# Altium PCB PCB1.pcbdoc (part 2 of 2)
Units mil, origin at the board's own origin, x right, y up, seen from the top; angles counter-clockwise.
Board outline 5175 x 2060 mil, 4 copper layers (Top Layer, Inner1, Inner2, Bottom Layer), stack 62.447 mil thick; 105 components, 59 nets, 317 pads, 174 vias.
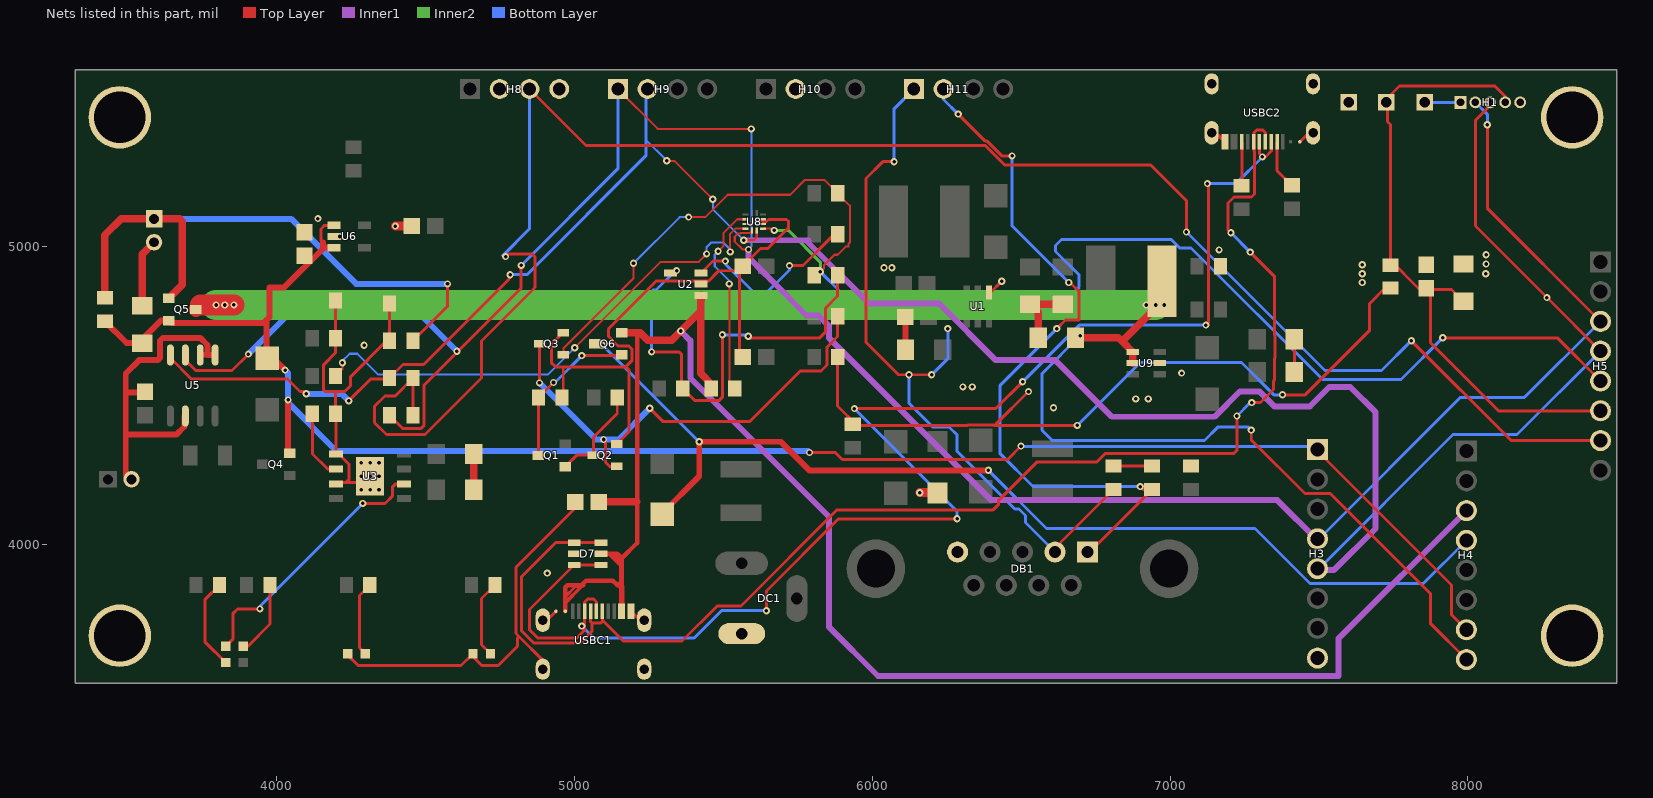
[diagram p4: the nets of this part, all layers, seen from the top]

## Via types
v1: diameter 24.02, hole 12, Top Layer to Bottom Layer, 174 vias

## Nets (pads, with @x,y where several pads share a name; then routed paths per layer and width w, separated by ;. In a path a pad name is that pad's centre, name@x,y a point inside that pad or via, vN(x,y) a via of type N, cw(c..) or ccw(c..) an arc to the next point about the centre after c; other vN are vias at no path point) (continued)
GND: C1.1 C2.1 C4.1 C5.1 C6.1 C7.2 C8.1 C9.1 C10.1 C11.1 C12.1 C13.2 C14.1 C15.1 C17.2 C18.2 C19.2 C20.1 D3.2 D7.2 DB1.5 DC1.2 H1.5 H3.8 H8.2 H8.4 H10.2 H13.1 LED1-1.1 LED1.2 LED3.1 Q2.2 Q3.2 R4.2 R5.2 R9.2 R13.2 R18.1 R20.2 R31.2 R32.2 SCREW1.1 SCREW2.1 SCREW3.1 SCREW4.1 U1.4 U2.2 U3.1 U3.3 U3.9 U4.2 U5.1 U5.2 U5.6 U6.2 U7.2 U8.5 U8.10 U8.11 U9.2 USBC1.1 USBC1.2 USBC1.3 USBC1.4 USBC1.A1B12 USBC1.B1A12 USBC2.1 USBC2.2 USBC2.3 USBC2.4 USBC2.A1B12 USBC2.B1A12 | length 7052.8
  Top Layer w7.09: U8.5@5575.47,5077.13 5595.47,5077.13 5603.33,5085 5633.33,5085 ; U8.10@5634.53,5077.13 5633.33,5078.33 5633.33,5085 ; U8.11@5634.53,5092.87 5633.33,5091.68 5633.33,5085
  Top Layer w10: R18.1@4199.37,4820 R4.2@4199.37,4693.33 4199.37,4644.37 4159.37,4604.37 4159.37,4519.37 4163.74,4515 4199.37,4515 4199.37,4510.63 ; U3.3@4200.5,4205 4205.5,4210 4235,4210 ; LED1.2@4240.43,3635 4240.43,3629.57 4275,3595 4620.52,3595 4655.26,3629.74 4690,3595 4745,3595 4810,3660 4810,3687.87 4814.72,3692.59 ; v1(4315,4230) 4295,4210 4235,4210 ; R5.2@4380.63,4810 R20.2@4380.63,4685 4370.63,4685 4250,4564.37 4250,4535 4230,4515 4200.63,4515 4200,4514.37 4200,4511.26 4199.37,4510.63 ; USBC1.3@4894.73,3582.59 4894.72,3612.59 4814.72,3692.59 ; USBC1.4@4894.73,3747.15 4908.77,3747.15 USBC1.A1B12@4939.02,3777.41 ; R9.2@4959.37,4495 4963.47,4499.09 4963.47,4597.72 ; Q3.2@4963.47,4712.4 4923.47,4672.4 4923.47,4611.53 4937.28,4597.72 4963.47,4597.72 ; C7.2@5005.63,4140 5005.63,4125.63 4804.72,3924.72 4804.72,3702.59 4814.72,3692.59 ; Q2.2@5143.47,4338.37 5183.46,4378.37 5183.46,4587.72 5173.46,4597.72 ; USBC1.B1A12@5190.98,3777.41 5221.24,3747.15 USBC1.1@5235.27,3747.15 ; C15.1@5565.63,4630 5555.63,4640 5555.63,4920 5485.63,4920 5450.63,4885 5275,4885 5115,4725 5115,4700 5147.28,4667.72 5183.46,4667.72 5193.46,4657.72 5193.46,4617.72 5173.46,4597.72 ; C6.1@5565.63,4935 5625.63,4995 5650,4995 5720,5065 5720,5085 5712.93,5092.07 5652.07,5092.07 U8.10@5640,5080 ; U1.4@6392.4,4847.24 6397.71,4847.24 v1(6435.47,4885) ; USBC2.1@7139.73,5382.85 7153.76,5382.85 USBC2.B1A12@7184.02,5352.59 ; C19.2@7417.7,4580 C18.2@7417.7,4690 ; USBC2.A1B12@7435.98,5352.6 7466.23,5382.85 USBC2.4@7480.27,5382.85 ; 4199.37,4510.63 R13.2@4199.37,4440 4200.5,4438.86 U3.1@4200.5,4305 4210,4305 4245,4270 4245,4220 4235,4210 ; 4963.47,4597.72 5173.46,4597.72
  Top Layer w20: U4.2@3514.37,4220 3510,4220 3495,4235 3495,4370 ; C9.1@3560,4514.37 3557.01,4511.38 3495,4511.38 ; U5.6@3695,4432.63 3692.35,4430 3692.35,4397.35 3665,4370 3495,4370 ; U5.2@3745,4637.37 3745.63,4637.99 3769.37,4637.99 ; U5.1@3795,4637.37 3770,4637.36 3769.37,4637.99 ; C2.1@6110.63,4765 6112.3,4763.33 C1.1@6112.3,4655 ; 3495,4370 3495,4511.38 ; 3495,4511.38 3495,4575 3540,4620 3602.57,4620 3610,4627.43 3610,4685 3620,4695 3745,4695 3769.37,4670.63 3769.37,4637.99
  Top Layer w25: C10.1@3550,4802.7 3550,4975.63 U7.2@3590,5015.63 ; C8.1@4662.7,4185 C20.1@4662.7,4290 ; C17.2@6557.3,4695 6557.3,4780 C4.1@6530,4807.3 C5.1@6640,4807.3
  Top Layer w30: v1(4400.02,5070) C12.1@4455.63,5070 ; v1(6160,4175) 6223.68,4175 D3.2@6225,4173.68
  other v1: 4910,3905 4285,4185 4315,4185 4345,4185 4285,4230 4345,4230 4285,4275 4315,4275 4345,4275 6609.01,4460 6885,4490 6926.88,4490 6305,4530 6336.11,4530 7038.74,4576.26 4295,4670 7645,4880.56 7645,4910 8060,4910 6040,4930 6066.69,4930 7645,4940 8061.16,4942.7 8061.16,4973.54 7165,4990 4213.5,5035.02 4140,5095
ID_INV: Q2.1 Q3.3 R11.2 | length 1618
  Top Layer w10: v1(4883.78,4543.56) 4883.78,4674.06 Q3.3@4884.73,4675 ; v1(5098.78,4353.57) 5105,4347.35 5105,4277.35 5118.78,4263.57 Q2.1@5143.47,4263.57 ; v1(5253.78,4458.57) 5298.78,4413.57 5588.78,4413.57 5758.78,4583.56 5828.78,4583.56 5848.78,4603.56 5848.78,4663.56 5884.37,4699.16 R11.2@5884.37,4767.5
  Bottom Layer w20: v1(4883.78,4543.56) 5073.78,4353.57 v1(5098.78,4353.57) 5148.78,4353.57 v1(5253.78,4458.57)
LED_CHG_A: LED4.1 R15.2 | length 309.2
  Top Layer w10: R15.2@3809.37,3865 3760.47,3816.1 3760.47,3675 LED4.1@3830.47,3605
LED_DONE_A: LED2.2 R16.2 | length 251.3
  Top Layer w10: LED2.2@3889.49,3660.01 3905,3660 3979.37,3734.37 R16.2@3979.37,3865
LED_EXT_A: LED1-1.2 LED1.1 R12.2 | length 252.7
  Top Layer w10: LED1.1@4299.57,3635 4279.56,3655 4279.56,3830.2 R12.2@4314.37,3865
LED_ON_A: LED3.2 R29.2 | length 261
  Top Layer w10: LED3.2@4719.49,3635.01 4689.49,3665 4689.49,3820.12 R29.2@4734.37,3865
PROG: R13.1 U3.2 | length 234.9
  Top Layer w10: R13.1@4120.63,4440 4121.88,4438.75 4121.88,4305 4171.88,4255 U3.2@4200.5,4255
PWR_SW_G: Q5.1 R19.2 R20.1 U7.1 | length 2088.3
  Top Layer w10: R20.1@4459.37,4685 4575,4800.63 v1(4575,4876.01)
  Top Layer w25: R19.2@3425,4829.37 3425,5040 3480,5095 3589.37,5095 U7.1@3590,5094.37 3675.63,5094.37 3685,5085 3685,4872.68 Q5.1@3639.72,4827.4
  Bottom Layer w20: U7.1@3590,5094.37 4050,5094.37 4268.36,4876.01 v1(4575,4876.01)
Q2_G: Q1.1 Q2.3 R10.2 | length 337.7
  Top Layer w10: Q1.1@4970.27,4262.6 5008.65,4300.97 Q2.3@5064.73,4300.97 5064.72,4360.97 5144.72,4440.97 5144.72,4494.64 R10.2@5144.37,4495
RS485_A: DB1.1 H11.2 R30.1 | length 2439.2
  Top Layer w10: v1(6289.38,5445.63) 6380,5355 6386.21,5355 6435.59,5305.63 v1(6470,5305.63) ; v1(6620,4725.63) 6649.37,4755 6695,4755 6695,4850 6664.37,4880.63 v1(6660,4880.63) ; DB1.1@6723.11,3975.9 6730.28,3975.9 R30.1@6940,4185.63 6910,4185.63 v1(6900,4195.63)
  Bottom Layer w10: H11.2@6240,5530 6240,5495 v1(6289.38,5445.63) ; v1(6470,5305.63) 6470,5070.63 v1(6660,4880.63) ; v1(6620,4725.63) 6430,4535.63 6430,4305.63 6540,4195.63 v1(6900,4195.63)
RS485_B: DB1.2 H11.1 R28.2 | length 2510.3
  Top Layer w10: v1(6074.06,5285.9) 6035.9,5285.9 5980,5230 5980,4680 6089.1,4570.9 v1(6124.06,4570.9) v1(6200,4570.9) ; DB1.2@6614.05,3975.9 6614.06,3989.68 R28.2@6810,4185.63
  Bottom Layer w10: v1(6074.06,5285.9) 6074.06,5464.06 H11.1@6140,5530 ; v1(6124.06,4570.9) 6124.06,4475.17 6203.39,4395.84 6257.99,4395.84 6285.54,4368.29 6285.54,4313.69 6479.24,4120 6493.38,4120 6515,4098.37 6515,4074.96 DB1.2@6614.05,3975.9 ; v1(6200,4570.9) 6254.06,4624.96 v1(6254.06,4725.9)
SCL: H1.3 H3.5 H5.4 H9.2 R25.1 U5.4 U8.8 | length 8216.2
  Top Layer w7.09: v1(5310.63,5288.99) 5336.64,5288.99 v1(5465.45,5160.18) ; v1(5569.48,5022.35) 5602.98,5022.35 5612.87,5032.24 U8.8@5612.87,5055.47
  Top Layer w10: U5.4@3645,4637.37 3645,4626.93 3715,4556.93 4038.07,4556.93 4080,4515 4093,4515 v1(4101.07,4506.93) ; v1(4243.72,4483.35) 4317.29,4556.93 4377.56,4556.93 R25.1@4380.63,4560 4425.63,4605 4495,4605 4777,4887 4777,4887.73 4785.16,4895.89 v1(4785.16,4906.64) ; H1.3@8075,5485 8075,5475 8025,5425 8025,5070 v1(8265,4830) H5.4@8445,4650
  Inner1 w20: v1(5569.48,5022.35) 5784.79,5022.35 5786.07,5021.07 ; 5780,5020 5990,4810 6225,4810 6415,4620 6615,4620 6805,4430 7150,4430 7235,4515 7300,4515 7350,4465 7470,4465 7535,4530 7605,4530 7690,4445 7690,4055 7550,3915 H3.5@7495,3915
  Bottom Layer w7.09: 5240.63,5360 5310.63,5290 v1(5310.63,5288.99) ; v1(5465.45,5160.18) 5465.45,5126.38 v1(5569.48,5022.35)
  Bottom Layer w10: v1(4785.16,4906.64) 4841.64,4906.64 5240.63,5305.63 5240.63,5360 5240.63,5523.96 H9.2@5246.67,5530 ; H3.5@7495,3915 7950,4370 8165,4370 H5.4@8445,4650
  Bottom Layer w20: v1(4101.07,4506.93) 4220.14,4506.93 v1(4243.72,4483.35)
SDA: H1.2 H3.4 H5.3 H9.1 R24.1 U5.3 U8.7 | length 8186.7
  Top Layer w7.09: H9.1@5146.67,5530 5280.66,5396.01 v1(5594.73,5396.01) ; v1(5585.24,4991.39) 5565.46,4991.39 5539.25,5017.6 5539.25,5034.25 5550,5045 5557.41,5045 5559.31,5046.9 5589.78,5046.9 5595.96,5053.08 5595.96,5054.3 U8.7@5597.13,5055.47
  Top Layer w10: U5.3@3695,4637.37 3695,4620 3730,4585 3851.67,4585 v1(3906.67,4640) ; R24.1@4380.63,4435 4425.63,4390 4485,4390 4496.67,4401.67 4496.67,4536.67 4822.37,4862.37 v1(4822.37,4937.74) ; v1(8065,5410) 8065,5130 H5.3@8445,4750
  Inner1 w20: v1(5585.24,4991.39) 5585.24,4964.76 5638.17,4911.83 5638.58,4911.83 5642.99,4907.42 5643.17,4907.42 5660.74,4889.84 5660.74,4889.26 5780,4770 5820,4770 5855,4735 5855,4695 6400,4150 7360,4150 H3.4@7495,4015
  Bottom Layer w7.09: v1(5585.24,4991.39) 5594.73,5000.88 v1(5594.73,5396.01)
  Bottom Layer w10: v1(4822.37,4937.74) 5146.67,5262.03 H9.1@5146.67,5530 ; H3.4@7500.63,4015 7495,4015 7975,4495 8190,4495 H5.3@8445,4750 ; H1.2@8025,5485 8065,5445 v1(8065,5410)
  Bottom Layer w20: v1(3906.67,4640) 4041.67,4775 4481.67,4775 v1(4606.67,4650)
SENS_PWR: C13.1 C14.2 H1.4 H5.6 H12.1 L2.2 | length 2146.5
  Top Layer w10: H12.1@7726.37,5485.98 H12.1@7730,5482.35 ; C13.1@7985,4817.3 7945,4857.3 C14.2@7875,4857.3 ; H1.4@8125,5485 8125,5505 8090,5540 7770,5540 7730,5500 H12.1@7730,5482.35 ; H5.6@8445,4450 8102.3,4450 7875,4677.3 C14.2@7875,4857.3 ; H12.1@7730,5482.35 7730,5420.48 7740,5410.48 7740,4955 7834.37,4860.63 7861.99,4860.63 7865.33,4857.3 C14.2@7875,4857.3
SENS_SEL: L2.1 R26.2 R27.2 | length 2536
  Top Layer w10: R26.2@5884.37,4630 5884.37,4465.72 5948.88,4401.21 6320.83,4401.21 cw(c6325.63,4390.21) 6325.63,4402.21 6404.37,4402.21 cw(c6404.37,4390.21) 6409.17,4401.21 6688.28,4401.21 v1(6688.64,4400.84) ; 6415,4404.37 v1(6525,4514.37) ; v1(7377.54,4503.71) 7453.71,4503.71 7670,4720 7670,4810 7721.96,4861.96 L2.1@7740,4861.96
  Bottom Layer w10: v1(6688.64,4400.84) 6899.76,4611.96 7240,4611.96 7348.26,4503.71 v1(7377.54,4503.71)
SINK_G: Q1.3 Q6.1 R9.1 | length 534.1
  Top Layer w10: Q1.3@4879.73,4300 4879.73,4494.09 R9.1@4880.63,4495 v1(4930.63,4545) ; v1(5025.63,4635) 5157.67,4635 Q6.1@5160.27,4637.6
  Bottom Layer w10: v1(4930.63,4545) 4935.63,4545 v1(5025.63,4635)
SRC_EN_N: R6.2 R7.2 U2.4 | length 1461
  Top Layer w10: v1(5260,4647.49) 5352.51,4647.49 5360,4640 5360,4529.37 R7.2@5364.37,4525 5404.37,4485 5487.21,4485 5497.44,4495.23 v1(5497.44,4705) ; v1(5584.37,4700) 5589.37,4695 5814.06,4694.94 ; 5814.13,4695 5824.37,4695 5844.37,4715 5844.37,4795 5884.37,4835 R6.2@5884.37,4905
  Bottom Layer w10: v1(5260,4647.49) 5260,4850.08 5264.92,4855 5275,4855 v1@5340,4920 ; v1(5497.44,4705) 5579.37,4705 v1(5584.37,4700)
  other v1: 5343.9,4920.27
STDBY_N: LED2.1 U3.6 | length 897.7
  Top Layer w10: LED2.1@3830.51,3659.99 3855.51,3685 3855.51,3770.51 3870,3785 v1(3945.51,3785) ; v1(4290.51,4139.03) 4364.91,4139.03 4390.88,4165 4390.88,4195 4400.88,4205 U3.6@4429.5,4205
  Bottom Layer w10: v1(3945.51,3785) 3945.51,3794.03 v1(4290.51,4139.03)
SYS: C10.2 C11.2 D5.1 H3.1 H4.7 Q4.2 Q5.2 R19.1 U6.1 U6.3 | length 5981.9
  Top Layer w10: 4157.07,5014.36 4150,5021.43 4150,5060 4162.39,5072.39 U6.1@4193.82,5072.39 ; v1(5790,4310.01) 5876.6,4310.01 5899.99,4286.61 6454.99,4286.61 v1(6499.99,4331.61) ; H3.1@7495,4315 7945,3865 7945,3765 H4.7@7995,3715
  Top Layer w20: R19.1@3425,4750.63 3498.33,4677.3 3537.3,4677.3 3612.6,4752.6 Q5.2@3639.72,4752.6 3647.96,4744.36 3957.07,4744.36 3967.07,4754.36 ; v1(4030,4586.61) 3990,4626.61 D5.1@3970,4626.61 3967.07,4629.54 3967.07,4754.36 ; v1(4040,4486.61) 4040,4312.68 Q4.2@4045.28,4307.4 ; 4157.07,5000.22 4159.68,4997.61 U6.3@4193.82,4997.61 ; 4157.07,5014.36 4157.07,4994.36 4027.07,4864.36 3977.07,4864.36 3977.07,4764.36 3967.07,4754.36
  Bottom Layer w10: v1(6499.99,4331.61) 6501.61,4330 7480,4330 H3.1@7495,4315
  Bottom Layer w20: v1(4030,4586.61) 4040,4576.61 v1(4040,4486.61) 4040,4476.61 4201.61,4315 5785,4315 v1(5790,4310.01)
SYS_SW: C17.1 H4.8 L3.1 Q5.3 U9.4 U9.5 | length 6011.1
  Top Layer w10: C17.1@6690.74,4695 v1(6698.21,4702.48) ; v1(7272.7,4385) 7272.7,4352.3 7453,4172 7538,4172 7875,3835 7875,3735 H4.8@7995,3615
  Top Layer w25: C17.1@6682.7,4695 6827.16,4695 6839.25,4682.91 ; U9.5@6874.76,4610 U9.4@6874.76,4647.4 6839.25,4682.91 ; L3.1@6956.49,4800.14 6839.25,4682.91 ; L3.1@6972.48,4816.14 L3.1@6972.48,4885
  Top Layer w50: Q5.3@3730.28,4790 Q5.3@3745.28,4805
  Top Layer w70: Q5.3@3745.28,4805 v1(3798.21,4805) v1(3827.37,4805) 3857.64,4805 v1(3858,4805.36)
  Inner2 w100: v1(3798.21,4805) v1(3827.37,4805) 5596.14,4805 5596.32,4804.81 5655.15,4804.81 5655.33,4805 v1(6920,4805) v1(6951.63,4805)
  Bottom Layer w10: v1(6698.21,4702.48) 6570,4574.26 6570,4385 6604.39,4350.61 7115.61,4350.61 7160,4395 7262.7,4395 v1(7272.7,4385)
  other v1: 6980,4805
TERM_B: R28.1 R30.2 | length 130
  Top Layer w10: R28.1@6810,4264.37 R30.2@6940,4264.37
TUSB_INT: R3.2 U8.6 | length 1735.5
  Top Layer w7.09: R3.2@4199.37,4566.67 4221.99,4589.29 v1(4221.99,4611.38) ; v1(5001.99,4661.38) 5290.61,4950 5418.28,4950 v1(5444.66,4976.38) ; v1(5523.77,4983.16) 5523.77,5043.77 5541.38,5061.38 U8.6@5575.47,5061.38
  Bottom Layer w7.09: v1(4221.99,4611.38) 4221.99,4616.99 4246.38,4641.38 4271.99,4641.38 4341.99,4571.38 4911.99,4571.38 v1(5001.99,4661.38) ; v1(5444.66,4976.38) 5444.66,4999.66 5460,5015 5500,5015 5523.77,4991.23 v1(5523.77,4983.16)
UPDI: H1.1 H7.1 | length 120.4
  Bottom Layer w10: H7.1@7855,5485.98 7855.98,5485 H1.1@7975,5485
USB_DN: D7.3 D7.4 USBC1.A7 USBC1.B7 USBC2.A7 USBC2.B7 | length 4881.7
  Top Layer w10: v1(5025.47,3727.41) 5035.47,3737.41 ; USBC1.A7@5074.84,3777.41 5075.47,3778.03 5075.47,3808 5065.47,3818 5045.47,3818 5035.47,3808 USBC1.B7@5035.47,3777.41 5035.47,3737.41 ; D7.4@5090.24,3932.6 D7.3@4999.76,3932.6 4850,3782.84 4850,3715 4877.59,3687.41 5008.85,3687.41 5035.47,3714.02 5035.47,3737.41 ; v1(5645.47,3778.99) 5645.47,3845.47 5887.4,4087.4 v1(6285.47,4087.4) ; v1(5940.47,4457.4) 6415.47,4457.4 v1(6505.47,4547.4) ; v1(7120.46,4737.4) 7130,4746.94 7130,5207.87 v1(7125.46,5212.4) ; USBC2.A7@7300.16,5352.59 7300.16,5312.1 v1(7310.16,5302.1) 7320.16,5302.1 7340.16,5322.1 7340.16,5351.96 USBC2.B7@7339.53,5352.59
  Bottom Layer w10: v1(5025.47,3727.41) 5065.47,3687.41 5402.95,3687.41 5494.54,3778.99 v1(5645.47,3778.99) ; v1(5940.47,4457.4) 6285.47,4112.4 v1(6285.47,4087.4) ; v1(6505.47,4547.4) 6695.47,4737.4 v1(7120.46,4737.4) ; v1(7125.46,5212.4) 7220.46,5212.4 v1(7310.16,5302.1)
USB_DP: D7.1 D7.6 USBC1.A6 USBC1.B6 USBC2.A6 USBC2.B6 | length 4692.3
  Top Layer w10: USBC1.A6@5055.16,3777.41 5055.16,3742 5059.76,3737.4 ; D7.6@5090.24,4007.4 D7.1@4999.76,4007.4 4937.4,4007.4 4823.93,3893.93 4823.93,3711.23 4865.16,3670 5020,3670 5059.76,3709.76 5059.76,3737.4 ; USBC1.B6@5094.53,3777.41 5094.53,3747.41 ; v1(7204.53,5047.4) 7194.53,5057.4 7194.53,5147.4 7214.53,5167.4 7273.25,5167.4 7283.25,5177.4 7283.25,5321.03 7282.25,5322.03 7282.25,5383.16 7292.28,5393.19 7310.47,5393.19 7320.47,5383.19 7320.47,5353.22 USBC2.A6@7319.84,5352.59 ; v1(7224.53,4432.4) 7224.53,4317.4 7214.53,4307.4 6783.27,4307.4 6753.27,4277.4 6552.4,4277.4 6425,4150 6425,4135.86 6406.55,4117.4 5882.4,4117.4 5560,3795 5480,3795 5362.41,3677.41 5164.53,3677.41 5094.53,3747.41 ; v1(7269.53,4982.4) 7350,4901.93 7350,4706.1 7352.53,4703.57 7352.53,4626.43 7350,4623.9 7350,4552.88 7347.53,4550.41 7347.53,4521.43 7303.51,4477.4 v1(7274.53,4477.4) ; 5059.76,3737.4 5089.76,3737.4 5094.53,3742.17 5094.53,3747.41
  Bottom Layer w10: v1(7204.53,5047.4) v1(7269.53,4982.4) ; v1(7224.53,4432.4) 7269.53,4477.4 v1(7274.53,4477.4)
USB_ID: H5.5 Q3.1 R2.2 R6.1 U8.9 | length 5100.5
  Top Layer w6: U8.9@5634.53,5061.38 5665.9,5061.38 v1(5671.75,5055.53)
  Top Layer w7.09: Q3.1@4963.47,4637.6 4964.37,4638.51 4964.37,4660 5199.37,4895 v1(5199.37,4945) ; v1(5384.37,5100) 5440,5100 5515,5175 5725,5175 5775,5225 5839.37,5225 R2.2@5884.37,5180 5925.63,5138.74 5925.63,5015 5920.88,5010.25 5920.88,5000.88 5920.75,5000.75 5911.38,5000.75 5884.31,4973.68 5873.68,4973.68 5838.52,4938.52 5838.52,4927.89 R6.1@5815.63,4905
  Top Layer w10: R6.1@5805.63,4905 5815.63,4905 5815.63,4905.93 v1(5826.13,4916.43) ; v1(7915.62,4695) 8300,4695 H5.5@8445,4550
  Inner2 w10: v1(5671.75,5055.53) 5719.47,5055.53 5826.13,4948.87 v1(5826.13,4916.43)
  Bottom Layer w7.09: v1(5199.37,4945) 5354.37,5100 v1(5384.37,5100)
  Bottom Layer w10: v1(5826.13,4916.43) 5897.56,4845 6675,4845 6695,4865 6695,4905.63 6615.63,4985 6615.63,5005 6635.63,5025 7004.37,5025 7032.67,4996.7 7070.8,4996.7 7512.5,4555 7775.62,4555 v1(7915.62,4695)
USB_OC_N: R8.2 U2.3 | length 615.4
  Top Layer w10: U2.3@5426.19,4912.4 5466.18,4952.4 v1(5507.84,4952.4) ; v1(5722.84,4937.4) 5767.84,4937.4 5872.84,5042.4 R8.2@5884.27,5042.4
  Bottom Layer w10: v1(5507.84,4952.4) 5507.84,4942.16 5605,4845 5645,4845 5722.84,4922.84 v1(5722.84,4937.4)
VBUS_DET: R1.2 U8.4 | length 654.8
  Top Layer w7.09: v1(5483.32,4985.33) 5501.99,5003.99 5501.99,5046.99 5547.87,5092.87 U8.4@5575.47,5092.87 ; v1(5520.62,4876.01) 5521.99,4874.64 5521.99,4542.38 R1.2@5539.37,4525
  Bottom Layer w7.09: v1(5483.32,4985.33) 5471.99,4973.99 5471.99,4934.66 5520.62,4886.03 v1(5520.62,4876.01)
VBUS_EXT: C7.1 D7.5 H4.3 Q6.2 R1.1 U2.1 USBC1.A4B9 USBC1.B4A9 | length 6528
  Top Layer w10: 4970.51,3804.17 5026.34,3860 ; 4970.51,3807.41 5023.1,3860 ; 4970.51,3825.51 5005,3860 5023.1,3860 ; 5031.34,3865 5026.34,3860 ; 5116.34,3970 5156.34,3930 ; 5126.34,3970 5127.92,3968.42 ; 5130.24,3970 5160,3940.24 5160.24,3940 ; 5144.5,3865 5149.5,3860 ; 5159.5,3860.5 5159.5,3850.74 ; 5159.5,3940 5127.92,3968.42 ; 5160.24,3850 5159.5,3850.74 ; 5023.1,3860 5026.34,3860 ; 5127.92,3968.42 5156.34,3940 5156.34,3930 ; 5149.5,3860 5150.24,3860 5156.34,3853.9 ; 5149.5,3860 5156.34,3853.16 ; 5156.34,3853.16 5156.34,3853.9 ; 5156.34,3853.16 5156.34,3850 5156.34,3780.56 USBC1.B4A9@5159.49,3777.41 5159.5,3850 ; 5156.34,3853.16 5157.92,3851.58 5159.5,3850 ; 5156.34,3853.9 5159.5,3850.74 ; 5156.34,3853.9 5156.34,3863.66 5156.34,3930 ; 5159.5,3850 5159.5,3850.74
  Top Layer w15: USBC1.A4B9@4970.51,3777.4 4970.51,3804.17 4970.51,3807.41 4970.51,3825.51 4970.51,3857.93 4977.58,3865 5031.34,3865 5031.34,3871.34 5040,3880 5130,3880 5144.75,3865.25 ; D7.5@5090.24,3970 5090.85,3970.61 5144.39,3970.61 5160,3955 ; 5144.5,3865 5144.75,3865.25 ; USBC1.B4A9@5159.49,3777.41 5162.07,3779.98 5162.07,3860 5160,3860 ; 5211.09,4712.4 5211.09,4144.37 5211.09,4006.09 5160,3955 ; 5144.75,3865.25 5149.5,3870 5150,3870 5156.34,3863.66 5159.5,3860.5 5160,3860 ; 5160,3860 5160,3940.24 5160,3955
  Top Layer w25: C7.1@5084.37,4140 5088.74,4144.37 5211.09,4144.37 ; Q6.2@5160.27,4712.4 5211.09,4712.4 5221.97,4712.4 5246.97,4687.4 5327.4,4687.4 v1(5357.68,4717.68) 5425,4785 ; R1.1@5460.63,4540 5425,4575.63 5425,4785 ; 5425,4785 5425,4820 ; 5425,4820 5425,4836.41 U2.1@5426.19,4837.6 5426.19,4821.19 5425,4820
  Inner1 w20: v1(5357.68,4717.68) 5390,4685.37 5390,4560 5855,4095 5855,3725 6020,3560 7565,3560 7565,3685 H4.3@7995,4115
  Bottom Layer w10: H4.3@7985,4095 H4.3@7995,4105
VBUS_SINK: D8.2 H4.4 Q6.3 | length 3613.2
  Top Layer w10: Q6.3@5069.73,4675 5075,4669.72 v1(5095,4669.72)
  Top Layer w20: D8.2@5295,4103.39 5295,4104.99 5420,4230 v1(5420,4346.01) 5693.99,4346.01 5789.7,4250.3 v1(6390.31,4250.3)
  Bottom Layer w10: v1(5095,4669.72) 5418.72,4346.01 v1(5420,4346.01) ; v1(6390.31,4250.3) 6585.61,4055 7285,4055 7470,3870 7850,3870 H4.4@7995,4015
WS_CC1: R22-2.2 R22.2 USBC2.A5 | length 168.5
  Top Layer w10: USBC2.A5@7359.21,5352.59 7359.21,5255.95 R22.2@7410,5205.15
WS_CC2: R23-1.2 R23.2 USBC2.B5 | length 147.9
  Top Layer w10: R23.2@7240,5205.15 7241.1,5206.25 USBC2.B5@7241.1,5352.59
WS_VOUT: H5.7 H8.3 R24.2 R25.2 | length 6226.8
  Top Layer w10: R24.2@4459.37,4435 R25.2@4459.37,4560 4399.37,4500 4365,4500 4330,4465 4330,4410 4370,4370 4499.71,4370 4689.37,4559.66 4689.37,4684.37 4868.47,4863.47 4868.47,4966.65 4858.47,4976.65 4779.26,4976.65 v1(4770.15,4967.53) ; H8.3@4850,5530 5040,5340 6380,5340 6445,5275 6935,5275 7055,5155 v1(7055,5050) ; v1(7809.99,4685) 8144.99,4350 H5.7@8445,4350
  Bottom Layer w10: v1(4770.15,4967.53) 4767.05,4970.63 4760,4970.63 4850,5060.63 H8.3@4850,5530 ; v1(7055,5050) 7520,4585 7709.99,4585 v1(7809.99,4685)
pads on no net: DB1.3 DC1.3 H8.1 U6.4 U8.3 U9.6 USBC1.A8 USBC1.B8 USBC2.A8 USBC2.B8

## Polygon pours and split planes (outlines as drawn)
GND on Top Layer (solid, remove dead copper, pour order 0): 3290,5740 3290,3480 8575,3480 8575,5740
GND on Bottom Layer (solid, remove dead copper, pour order 4): 3260,5655 3260,3390 8590,3390 8590,5655
5V_IN on Inner1 (solid, remove dead copper): 3265,5660 3265,3475 8575,3475 8575,5660
GND on Inner2 (solid, remove dead copper): 3250,5655 3250,3400 8840,3400 8840,5655

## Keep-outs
Board Outline Layer:
  region: 3687.5,5320 ccw(c3687.5,5270) 3637.5,5270 ccw(c3687.5,5270) 3687.5,5220 3942.5,5220 ccw(c3942.5,5270) 3992.5,5270 ccw(c3942.5,5270) 3942.5,5320
  region: 3687.5,5320 ccw(c3687.5,5270) 3637.5,5270 ccw(c3687.5,5270) 3687.5,5220 3942.5,5220 ccw(c3942.5,5270) 3992.5,5270 ccw(c3942.5,5270) 3942.5,5320
  region: 4472.5,5320 ccw(c4472.5,5270) 4422.5,5270 ccw(c4472.5,5270) 4472.5,5220 4727.5,5220 ccw(c4727.5,5270) 4777.5,5270 ccw(c4727.5,5270) 4727.5,5320
  region: 4472.5,5320 ccw(c4472.5,5270) 4422.5,5270 ccw(c4472.5,5270) 4472.5,5220 4727.5,5220 ccw(c4727.5,5270) 4777.5,5270 ccw(c4727.5,5270) 4727.5,5320
  region: 3687.5,4070 ccw(c3687.5,4020) 3637.5,4020 ccw(c3687.5,4020) 3687.5,3970 3942.5,3970 ccw(c3942.5,4020) 3992.5,4020 ccw(c3942.5,4020) 3942.5,4070
  region: 3687.5,4070 ccw(c3687.5,4020) 3637.5,4020 ccw(c3687.5,4020) 3687.5,3970 3942.5,3970 ccw(c3942.5,4020) 3992.5,4020 ccw(c3942.5,4020) 3942.5,4070
  region: 4472.5,4070 ccw(c4472.5,4020) 4422.5,4020 ccw(c4472.5,4020) 4472.5,3970 4727.5,3970 ccw(c4727.5,4020) 4777.5,4020 ccw(c4727.5,4020) 4727.5,4070
  region: 4472.5,4070 ccw(c4472.5,4020) 4422.5,4020 ccw(c4472.5,4020) 4472.5,3970 4727.5,3970 ccw(c4727.5,4020) 4777.5,4020 ccw(c4727.5,4020) 4727.5,4070
  region: 3830,3740 cw(c3805,3740) 3780,3740 cw(c3805,3740)
  circle w0.1: c3805,3740 r25
  region: 3830,3740 3829.62,3735.66 3828.49,3731.45 3826.65,3727.5 3824.15,3723.93 3821.07,3720.85 3817.5,3718.35 3813.55,3716.51 3809.34,3715.38 3805,3715 3800.66,3715.38 3796.45,3716.51 3792.5,3718.35 3788.93,3720.85 3785.85,3723.93 3783.35,3727.5 3781.51,3731.45 3780.38,3735.66 3780,3740 3780.38,3744.34 3781.51,3748.55 3783.35,3752.5 3785.85,3756.07 3788.93,3759.15 3792.5,3761.65 3796.45,3763.49 3800.66,3764.62 3805,3765 3809.34,3764.62 3813.55,3763.49 3817.5,3761.65 3821.07,3759.15 3824.15,3756.07 3826.65,3752.5 3828.49,3748.55 3829.62,3744.34
  region: 3930,3740 cw(c3905,3740) 3880,3740 cw(c3905,3740)
  circle w0.1: c3905,3740 r25
  region: 3930,3740 3929.62,3735.66 3928.49,3731.45 3926.65,3727.5 3924.15,3723.93 3921.07,3720.85 3917.5,3718.35 3913.55,3716.51 3909.34,3715.38 3905,3715 3900.66,3715.38 3896.45,3716.51 3892.5,3718.35 3888.93,3720.85 3885.85,3723.93 3883.35,3727.5 3881.51,3731.45 3880.38,3735.66 3880,3740 3880.38,3744.34 3881.51,3748.55 3883.35,3752.5 3885.85,3756.07 3888.93,3759.15 3892.5,3761.65 3896.45,3763.49 3900.66,3764.62 3905,3765 3909.34,3764.62 3913.55,3763.49 3917.5,3761.65 3921.07,3759.15 3924.15,3756.07 3926.65,3752.5 3928.49,3748.55 3929.62,3744.34
  region: 4248,3741.25 cw(c4223,3741.25) 4198,3741.25 cw(c4223,3741.25)
  circle w0.1: c4223,3741.25 r25
  region: 4248,3741.25 4247.62,3736.91 4246.49,3732.7 4244.65,3728.75 4242.15,3725.18 4239.07,3722.1 4235.5,3719.6 4231.55,3717.76 4227.34,3716.63 4223,3716.25 4218.66,3716.63 4214.45,3717.76 4210.5,3719.6 4206.93,3722.1 4203.85,3725.18 4201.35,3728.75 4199.51,3732.7 4198.38,3736.91 4198,3741.25 4198.38,3745.59 4199.51,3749.8 4201.35,3753.75 4203.85,3757.32 4206.93,3760.4 4210.5,3762.9 4214.45,3764.74 4218.66,3765.87 4223,3766.25 4227.34,3765.87 4231.55,3764.74 4235.5,3762.9 4239.07,3760.4 4242.15,3757.32 4244.65,3753.75 4246.49,3749.8 4247.62,3745.59
  region: 4348,3741.25 cw(c4323,3741.25) 4298,3741.25 cw(c4323,3741.25)
  circle w0.1: c4323,3741.25 r25
  region: 4348,3741.25 4347.62,3736.91 4346.49,3732.7 4344.65,3728.75 4342.15,3725.18 4339.07,3722.1 4335.5,3719.6 4331.55,3717.76 4327.34,3716.63 4323,3716.25 4318.66,3716.63 4314.45,3717.76 4310.5,3719.6 4306.93,3722.1 4303.85,3725.18 4301.35,3728.75 4299.51,3732.7 4298.38,3736.91 4298,3741.25 4298.38,3745.59 4299.51,3749.8 4301.35,3753.75 4303.85,3757.32 4306.93,3760.4 4310.5,3762.9 4314.45,3764.74 4318.66,3765.87 4323,3766.25 4327.34,3765.87 4331.55,3764.74 4335.5,3762.9 4339.07,3760.4 4342.15,3757.32 4344.65,3753.75 4346.49,3749.8 4347.62,3745.59
  region: 4664,3742.25 cw(c4639,3742.25) 4614,3742.25 cw(c4639,3742.25)
  circle w0.1: c4639,3742.25 r25
  region: 4664,3742.25 4663.62,3737.91 4662.49,3733.7 4660.65,3729.75 4658.15,3726.18 4655.07,3723.1 4651.5,3720.6 4647.55,3718.76 4643.34,3717.63 4639,3717.25 4634.66,3717.63 4630.45,3718.76 4626.5,3720.6 4622.93,3723.1 4619.85,3726.18 4617.35,3729.75 4615.51,3733.7 4614.38,3737.91 4614,3742.25 4614.38,3746.59 4615.51,3750.8 4617.35,3754.75 4619.85,3758.32 4622.93,3761.4 4626.5,3763.9 4630.45,3765.74 4634.66,3766.87 4639,3767.25 4643.34,3766.87 4647.55,3765.74 4651.5,3763.9 4655.07,3761.4 4658.15,3758.32 4660.65,3754.75 4662.49,3750.8 4663.62,3746.59
  region: 4764,3742.3 cw(c4739,3742.3) 4714,3742.3 cw(c4739,3742.3)
  circle w0.1: c4739,3742.3 r25
  region: 4764,3742.3 4763.62,3737.96 4762.49,3733.75 4760.65,3729.8 4758.15,3726.23 4755.07,3723.15 4751.5,3720.65 4747.55,3718.81 4743.34,3717.68 4739,3717.3 4734.66,3717.68 4730.45,3718.81 4726.5,3720.65 4722.93,3723.15 4719.85,3726.23 4717.35,3729.8 4715.51,3733.75 4714.38,3737.96 4714,3742.3 4714.38,3746.64 4715.51,3750.85 4717.35,3754.8 4719.85,3758.37 4722.93,3761.45 4726.5,3763.95 4730.45,3765.79 4734.66,3766.92 4739,3767.3 4743.34,3766.92 4747.55,3765.79 4751.5,3763.95 4755.07,3761.45 4758.15,3758.37 4760.65,3754.8 4762.49,3750.85 4763.62,3746.64
  lines w0.1: 3637.5,4020 cw(c3687.5,4020) 3687.5,4070 3942.5,4070 cw(c3942.5,4020) 3992.5,4020 cw(c3942.5,4020) 3942.5,3970 3687.5,3970 cw(c3687.5,4020) 3637.5,4020 ; 3637.5,5270 cw(c3687.5,5270) 3687.5,5320 3942.5,5320 cw(c3942.5,5270) 3992.5,5270 cw(c3942.5,5270) 3942.5,5220 3687.5,5220 cw(c3687.5,5270) 3637.5,5270 ; 4422.5,4020 cw(c4472.5,4020) 4472.5,4070 4727.5,4070 cw(c4727.5,4020) 4777.5,4020 cw(c4727.5,4020) 4727.5,3970 4472.5,3970 cw(c4472.5,4020) 4422.5,4020 ; 4422.5,5270 cw(c4472.5,5270) 4472.5,5320 4727.5,5320 cw(c4727.5,5270) 4777.5,5270 cw(c4727.5,5270) 4727.5,5220 4472.5,5220 cw(c4472.5,5270) 4422.5,5270
  lines w5: 3325,3535 3325,5595 8500,5595 8500,3535 3325,3535

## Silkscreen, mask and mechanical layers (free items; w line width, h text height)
Top Silkscreen Layer:
  lines w5: 3770,3564 3770,3704 3948,3704 3948,3564 3770,3564 ; 4185,3565.25 4185,3705.25 4363,3705.25 4363,3565.25 4185,3565.25 ; 4600,3566.25 4600,3706.25 4778,3706.25 4778,3566.25 4600,3566.25
  text "NC" at 4680,5389.9 h60 r90
  text "SCL" at 5276.67,5354.6 h60 r90
  text "GND" at 4776.2,5351.3 h60 r90
  text "GND" at 4980,5351.3 h60 r90
  text "GND" at 5775.47,5351.3 h60 r90
  text "SDA" at 5175,5349.7 h60 r90
  text "SCL" at 8095,5348.1 h45 r90
  text "GND" at 8205,5345.7 h45 r90
  text "SDA" at 8045,5344.4 h45 r90
  text "UPDI" at 7995,5335 h45 r90
  text "GND" at 7630,5320 h60 r90
  text "CANL" at 5378.33,5312.8 h60 r90
  text "CANH" at 5480,5309.5 h60 r90
  text "UPDI" at 7890,5305 h60 r90
  text "DB_DI1" at 5975,5268.1 h60 r90
  text "DB_DI0" at 5869.53,5253.4 h60 r90
  text "DB_DO1" at 6475,5242.1 h60 r90
  text "RS485B" at 6170,5235.5 h60 r90
  text "RS485A" at 6267.87,5232.3 h60 r90
  text "CHG_EN" at 6365.73,5229.1 h60 r90
  text "DB_COM" at 5670,5222.6 h60 r90
  text "SNS_PWR" at 8150,5219.1 h45 r90
  text "WS_VOUT" at 4872.4,5175.9 h60 r90
  text "SNS_PWR" at 7760,5145 h60 r90
  text "OUT TO / SENSOR" at 7960,5085 h60
  text "PWR_SW_G" at 3635,5055 h60
  text "GND" at 3635,4980 h60
  text "5V_OUT" at 8135,4920 h60
  text "SWITCH" at 3345,4860 h60
  text "3V3_AON" at 8093.2,4816.96 h60
  text "SDA" at 8260.5,4713.91 h60
  text "SCL" at 8265.4,4622.27 h60
  text "USB_ID" at 8141.4,4530.63 h60
  text "SENS_PWR" at 8056.2,4421.09 h60
  text "WS_VOUT" at 8086.7,4318.04 h60
  text "SYS" at 7310.3,4290 h60
  text "12V_IN" at 7723,4285 h60
  text "BATT +" at 3470,4280 h60 r90
  text "GND" at 3545,4280 h60 r90
  text "CHG_EN" at 8139.9,4215 h60
  text "5V_OUT" at 7184.8,4195.8 h60
  text "5V_DC" at 7724.1,4182.66 h60
  text "3V3_AON" at 7143,4090.2 h60
  text "VBUS_EXT" at 7610,4080.31 h60
  text "SDA" at 7310.3,3984.6 h60
  text "VBUS_SINK" at 7592.5,3977.97 h60
  text "SCL" at 7315.2,3890.4 h60
  text "5V_IN" at 7746.9,3875.63 h60
  text "CAN_H" at 7225,3796.2 h60
  text "GREEN" at 4630,3780 h45
  text "YELLOW" at 4190,3775 h45
  text "BAT_NODE" at 7606.8,3773.29 h60
  text "CAN_L" at 7228.3,3690.6 h60
  text "SYS" at 7807.8,3670.94 h60
  text "GREEN" at 3955,3640 h45
  text "GND" at 7311.9,3585 h60
  text "SYS_SW" at 7675.8,3580 h60
  text "RED" at 3960,3575 h45
Bottom Silkscreen Layer:
  drawing of 14 lines, arcs and shapes, not listed
  text "NC" at 4612.5,5391.5 h60 r270
  text "SCL" at 5209.17,5356.2 h60 r270
  text "GND" at 4708.7,5352.9 h60 r270
  text "GND" at 4912.5,5352.9 h60 r270
  text "GND" at 5707.97,5352.9 h60 r270
  text "SDA" at 5107.5,5351.3 h60 r270
  text "SCL" at 8047.5,5349.65 h45 r270
  text "GND" at 8157.5,5347.25 h45 r270
  text "SDA" at 7997.5,5345.95 h45 r270
  text "UPDI" at 7947.5,5336.55 h45 r270
  text "GND" at 7565,5317.7 h60 r270
  text "CANL" at 5310.83,5314.4 h60 r270
  text "CANH" at 5412.5,5311.1 h60 r270
  text "UPDI" at 7825,5302.7 h60 r270
  text "DB_DI1" at 5907.5,5269.7 h60 r270
  text "DB_DI0" at 5802.03,5255 h60 r270
  text "DB_DO1" at 6407.5,5243.7 h60 r270
  text "RS485B" at 6102.5,5237.1 h60 r270
  text "RS485A" at 6200.37,5233.9 h60 r270
  text "CHG_EN" at 6298.23,5230.7 h60 r270
  text "DB_COM" at 5602.5,5224.2 h60 r270
  text "SNS_PWR" at 8102.5,5220.65 h45 r270
  text "WS_VOUT" at 4804.9,5177.5 h60 r270
  text "SNS_PWR" at 7695,5142.7 h60 r270
  text "PWR_SW_G" at 3970,5055 h60
  text "GND" at 3740,4980 h60
  text "5V_OUT" at 8366.45,4922.5 h60
  text "3V3_AON" at 8366.45,4819.46 h60
  text "SDA" at 8366.45,4716.41 h60
  text "SCL" at 8366.45,4624.77 h60
  text "USB_ID" at 8366.45,4533.13 h60
  text "SENS_PWR" at 8366.45,4423.59 h60
  text "WS_VOUT" at 8366.45,4320.54 h60
  text "SYS" at 7417.95,4292.5 h60
  text "12V_IN" at 7921.25,4282.5 h60
  text "BATTERY +" at 3405,4280 h60 r270
  text "GND" at 3480,4280 h60 r270
  text "CHG_EN" at 8366.45,4217.5 h60
  text "5V_OUT" at 7417.95,4198.3 h60
  text "5V_DC" at 7921.25,4180.16 h60
  text "U4" at 3525,4120 h45
  text "3V3_AON" at 7417.95,4092.7 h60
  text "VBUS_EXT" at 7921.25,4077.81 h60
  text "RS485 A" at 6690,4034.1 h60 r270
  text "DB_D01" at 6365,4030.2 h60 r270
  text "RS485 B" at 6580,4030 h60 r270
  text "10/30/2026 / BEN KASPER / REV 1 / PPM METER BOARD PCB FILES - 26" at 5945,4025 h60
  text "GND" at 6255,4025 h60 r270
  text "SDA" at 7417.95,3987.1 h60
  text "VBUS_SINK" at 7921.25,3975.47 h60
  text "SCL" at 7417.95,3892.9 h60
  text "5V_IN" at 7921.25,3873.13 h60
  text "DC JACK 12V" at 5650,3835 h60
  text "DB_COM" at 6480,3812.8 h60 r90
  text "DB_DI1" at 6585,3812.8 h60 r90
  text "DB_DI0" at 6700,3812.8 h60 r90
  text "DB9_12V" at 6370,3807.8 h60 r90
  text "CAN_H" at 7417.95,3798.7 h60
  text "BAT_NODE" at 7921.25,3770.79 h60
  text "CAN_L" at 7417.95,3693.1 h60
  text "SYS" at 7921.25,3668.44 h60
  text "GND" at 5604.8,3600 h60
  text "GND" at 7417.95,3587.5 h60
  text "SYS_SW" at 7921.25,3577.5 h60
Mechanical Layer:
  circle w0.1: c3805,3740 r25
  circle w0.1: c3905,3740 r25
  circle w0.1: c4223,3741.25 r25
  circle w0.1: c4323,3741.25 r25
  circle w0.1: c4639,3742.25 r25
  circle w0.1: c4739,3742.3 r25
  lines w0.1: 3637.5,4020 cw(c3687.5,4020) 3687.5,4070 3942.5,4070 cw(c3942.5,4020) 3992.5,4020 cw(c3942.5,4020) 3942.5,3970 3687.5,3970 cw(c3687.5,4020) 3637.5,4020 ; 3637.5,5270 cw(c3687.5,5270) 3687.5,5320 3942.5,5320 cw(c3942.5,5270) 3992.5,5270 cw(c3942.5,5270) 3942.5,5220 3687.5,5220 cw(c3687.5,5270) 3637.5,5270 ; 4422.5,4020 cw(c4472.5,4020) 4472.5,4070 4727.5,4070 cw(c4727.5,4020) 4777.5,4020 cw(c4727.5,4020) 4727.5,3970 4472.5,3970 cw(c4472.5,4020) 4422.5,4020 ; 4422.5,5270 cw(c4472.5,5270) 4472.5,5320 4727.5,5320 cw(c4727.5,5270) 4777.5,5270 cw(c4727.5,5270) 4727.5,5220 4472.5,5220 cw(c4472.5,5270) 4422.5,5270
Document Layer:
  lines w10: 3760,3535 3945,3535 ; 3762.5,3435 3947.5,3435 ; 4183.12,3536.25 4368.12,3536.25 ; 4185.62,3436.25 4370.62,3436.25 ; 4606.25,3537.25 4791.25,3537.25 ; 4608.75,3437.25 4793.75,3437.25

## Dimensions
3325,5835 to 8490,5835 on Document Layer
3000,5595 to 3000,3535 on Document Layer
3165,5270 to 3165,4020 on Document Layer
4025,3704 to 4025,3740 on Document Layer
4435,3704 to 4435,3564 on Document Layer
3620,3740 to 3620,3634 on Document Layer
3420,3740 to 3420,3535 on Document Layer
3185,3740 to 3185,3435 on Document Layer
3770,3220 to 4185,3220 on Document Layer
4363,3215 to 4778,3215 on Document Layer
3770,3000 to 3948,3000 on Document Layer
3475,5680 to 3325,5680 on Document Layer
8350,5710 to 8500,5710 on Document Layer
